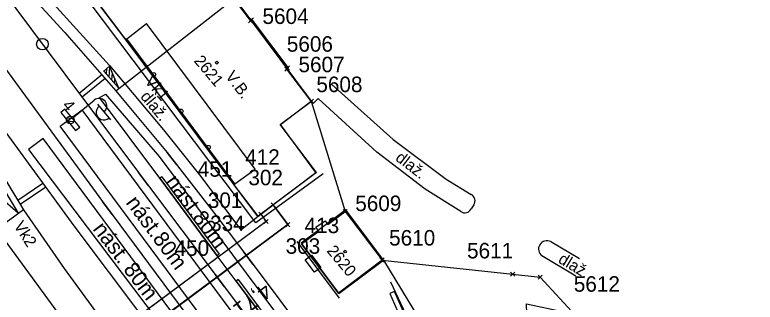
# Model space of a CAD drawing. Extents: x -804166 to -803706, y -1151030 to -1150147.
# Drawn here: x -804085.1 to -803989.6, y -1150250.1 to -1150213 of the extents above; entities that cross this region are included whole.
import ezdxf

# ---------------------------------------------------------------- set-up
doc = ezdxf.new("R2010")
doc.units = 0
for name, color, linetype in [('0381KM032-037P - Vrstva 1', 7, 'Continuous'), ('0381KM032-037P - Vrstva 12', 7, 'Continuous'), ('0381KM032-037P - Vrstva 14', 7, 'Continuous'), ('0381KM032-037P - Vrstva 16', 7, 'Continuous'), ('0381KM032-037P - Vrstva 17', 7, 'Continuous'), ('0381KM032-037P - Vrstva 23', 7, 'Continuous'), ('0381KM032-037P - Vrstva 25', 7, 'Continuous'), ('0381KM032-037P - Vrstva 3', 7, 'Continuous'), ('0381KM032-037P - Vrstva 33', 7, 'Continuous'), ('0381KM032-037P - Vrstva 4', 7, 'Continuous'), ('0381KM032-037P - Vrstva 51', 7, 'Continuous'), ('0381KM032-037P - Vrstva 55', 7, 'Continuous'), ('0381KM032-037P - Vrstva 57', 7, 'Continuous'), ('0381KM032-037P - Vrstva 59', 7, 'Continuous'), ('0381KM032-037P - Vrstva 7', 7, 'Continuous'), ('DZ_CD - CD', 7, 'Continuous'), ('DZ_CD - CD_krizek', 7, 'Continuous'), ('DZ_CD - CD_čísla', 7, 'Continuous'), ('szdc - hran DP', 7, 'Continuous'), ('szdc - szdc_cislo', 7, 'Continuous'), ('szdc - szdc_krizek', 7, 'Continuous'), ('VB - VB', 7, 'Continuous'), ('VB - VB_cislo', 7, 'Continuous'), ('VB - VB_krizek', 7, 'Continuous')]:
    doc.layers.add(name, color=color, linetype=linetype)

msp = doc.modelspace()

# ---------------------------------------------------------------- linework, layer by layer
at = {"layer": '0381KM032-037P - Vrstva 1'}
for points in [[(-804087.926, -1150205.285), (-804078.707, -1150215.283), (-804072.371, -1150222.524), (-804072.077, -1150222.855), (-804071.467, -1150223.584), (-804065.479, -1150230.817), (-804059.467, -1150238.509), (-804055.553, -1150243.678), (-804054.356, -1150245.269), (-804043.889, -1150259.222), (-804035.374, -1150270.613), (-804034.4, -1150271.93), (-804017.97, -1150293.92), (-804002.6, -1150314.46), (-803985.38, -1150337.43), (-803955.87, -1150376.72)], [(-804089.349, -1150206.442), (-804078.67, -1150220.695), (-804069.154, -1150233.375), (-804067.857, -1150235.106), (-804059.282, -1150246.533), (-804058.068, -1150248.156), (-804048.703, -1150260.645), (-804037.85, -1150275.13), (-804021.63, -1150296.76), (-804006.14, -1150317.336), (-803988.978, -1150340.287), (-803981.901, -1150349.725)], [(-804090.387, -1150214.375), (-804086.648, -1150219.546), (-804073.823, -1150237.114), (-804072.555, -1150238.826), (-804064.047, -1150250.31), (-804062.807, -1150251.974), (-804052.288, -1150266.049), (-804042.5, -1150279.11), (-804026.546, -1150300.334), (-804011.272, -1150320.629), (-803993.373, -1150344.487), (-803965.171, -1150382.072), (-803953.841, -1150397.189)], [(-804093.97, -1150217.423), (-804088.165, -1150225.674), (-804077.507, -1150240.279), (-804068.519, -1150252.214), (-804067.312, -1150253.815), (-804055.014, -1150270.122), (-804046.09, -1150281.931), (-804030.046, -1150303.209), (-804014.756, -1150323.518), (-803996.92, -1150347.354), (-803968.884, -1150385.416), (-803942.597, -1150419.033)], [(-804095.554, -1150218.377), (-804090.738, -1150227.081), (-804084.011, -1150238.21), (-804078.761, -1150245.777), (-804072.115, -1150254.848), (-804070.853, -1150256.555), (-804059.975, -1150271.287), (-804049.56, -1150285.37), (-804034.127, -1150306.216), (-804018.794, -1150326.862), (-804001.176, -1150350.631), (-803980.37, -1150378.683), (-803972.82, -1150388.417), (-803965.206, -1150397.597)], [(-804088.45, -1150239.448), (-804070.362, -1150264.071), (-804054.977, -1150285.047), (-804052.95, -1150287.79), (-804037.556, -1150308.636), (-804021.871, -1150329.906), (-804004.483, -1150353.558), (-803990.764, -1150372.094)]]:
    msp.add_lwpolyline(points, dxfattribs=at)
at = {"layer": '0381KM032-037P - Vrstva 12'}
for p, q in [((-804066.16, -1150233.938), (-804066.401, -1150234.117)), ((-804066.16, -1150233.938), (-804058.75, -1150243.944)), ((-804066.401, -1150234.117), (-804058.991, -1150244.123)), ((-804058.75, -1150243.944), (-804058.991, -1150244.123)), ((-804056.315, -1150247.214), (-804056.555, -1150247.394)), ((-804056.315, -1150247.214), (-804040.257, -1150268.603)), ((-804056.555, -1150247.394), (-804040.497, -1150268.783))]:
    msp.add_line(p, q, dxfattribs=at)
at = {"layer": '0381KM032-037P - Vrstva 14'}
for p, q in [((-804074.204, -1150223.733), (-804073.378, -1150223.272)), ((-804079.27, -1150227.397), (-804076.452, -1150225.306)), ((-804028.769, -1150289.524), (-804076.452, -1150225.306)), ((-804031.587, -1150291.616), (-804079.27, -1150227.397)), ((-804081.457, -1150229.022), (-804083.366, -1150230.42)), ((-804033.774, -1150293.241), (-804081.457, -1150229.022)), ((-804083.366, -1150230.42), (-804035.088, -1150294.233))]:
    msp.add_line(p, q, dxfattribs=at)
for points in [[(-804025.083, -1150286.789), (-804066.443, -1150231.313), (-804073.378, -1150223.272)], [(-804026.202, -1150287.61), (-804040.497, -1150268.783), (-804056.555, -1150247.394), (-804058.991, -1150244.123), (-804066.401, -1150234.117), (-804074.204, -1150223.733)]]:
    msp.add_lwpolyline(points, dxfattribs=at)
at = {"layer": '0381KM032-037P - Vrstva 16'}
msp.add_lwpolyline([(-804076.663, -1150208.439), (-804080.541, -1150211.102), (-804072.896, -1150219.59), (-804065.929, -1150227.882), (-804061.293, -1150233.691), (-804055.946, -1150240.785), (-804053.726, -1150239.037)], dxfattribs=at)
at = {"layer": '0381KM032-037P - Vrstva 17'}
msp.add_line((-804033.09, -1150255.012), (-804036.604, -1150247.549), dxfattribs=at)
at = {"layer": '0381KM032-037P - Vrstva 23'}
for p, q in [((-804076.663, -1150208.439), (-804070.854, -1150216.226)), ((-804046.83, -1150224.17), (-804057.749, -1150209.571)), ((-804054.575, -1150213.815), (-804054.464, -1150213.732)), ((-804049.846, -1150219.863), (-804054.464, -1150213.732)), ((-804070.683, -1150216.127), (-804068.144, -1150214.178)), ((-804054.098, -1150232.952), (-804068.144, -1150214.178)), ((-804056.826, -1150234.944), (-804070.739, -1150216.164)), ((-804056.727, -1150234.87), (-804070.683, -1150216.127)), ((-804049.977, -1150219.962), (-804049.846, -1150219.863)), ((-804050.874, -1150227.195), (-804046.83, -1150224.17)), ((-804046.171, -1150233.383), (-804050.874, -1150227.195)), ((-804056.727, -1150234.87), (-804054.098, -1150232.952)), ((-804046.171, -1150233.383), (-804053.726, -1150239.037)), ((-804056.727, -1150234.87), (-804056.827, -1150234.975)), ((-804053.726, -1150239.037), (-804056.827, -1150234.975)), ((-804042.401, -1150238.224), (-804048.187, -1150242.521)), ((-804037.56, -1150244.693), (-804042.401, -1150238.224)), ((-804048.747, -1150242.287), (-804043.271, -1150249.616))]:
    msp.add_line(p, q, dxfattribs=at)
for points in [[(-804045.335, -1150233.577), (-804053.998, -1150239.883), (-804077.772, -1150208.366)], [(-804070.854, -1150216.226), (-804070.854, -1150216.226), (-804070.739, -1150216.164), (-804070.683, -1150216.127)], [(-804048.187, -1150242.521), (-804043.318, -1150249.006), (-804037.56, -1150244.693)]]:
    msp.add_lwpolyline(points, dxfattribs=at)
msp.add_lwpolyline([(-804078.654, -1150225.237), (-804079.177, -1150225.666), (-804077.274, -1150227.98), (-804076.752, -1150227.551)], close=True, dxfattribs=at)
for centre in [(-804067.178, -1150220.749), (-804063.65, -1150225.47), (-804060.146, -1150230.138)]:
    msp.add_circle(centre, 0.25, dxfattribs=at)
at = {"layer": '0381KM032-037P - Vrstva 25'}
for p, q in [((-804077.58, -1150226.29), (-804074.886, -1150224.056)), ((-804074.439, -1150224.595), (-804072.779, -1150226.596)), ((-804078.454, -1150226.704), (-804077.501, -1150226.793)), ((-804078.382, -1150226.334), (-804077.507, -1150226.416))]:
    msp.add_line(p, q, dxfattribs=at)
msp.add_lwpolyline([(-804047.64, -1150244.642), (-804046.836, -1150244.048), (-804045.648, -1150245.658), (-804046.452, -1150246.252), (-804047.64, -1150244.642)], dxfattribs=at)
msp.add_circle((-804077.965, -1150226.609), 0.5, dxfattribs=at)
msp.add_circle((-804077.965, -1150226.609), 0.5, dxfattribs=at)
for centre, start, end in [((-804074.247, -1150224.826), 309.66205, 129.66205), ((-804073.619, -1150225.603), 128.95947, 310.36462)]:
    msp.add_arc(centre, 1, start, end, dxfattribs=at)
at = {"layer": '0381KM032-037P - Vrstva 3'}
for p, q in [((-804072.077, -1150222.855), (-804041.236, -1150198.773)), ((-804073.637, -1150220.313), (-804073.63, -1150220.295)), ((-804073.297, -1150220.702), (-804073.235, -1150219.95)), ((-804072.951, -1150221.097), (-804072.856, -1150219.757)), ((-804072.606, -1150221.492), (-804072.534, -1150220.523)), ((-804072.26, -1150221.887), (-804072.219, -1150221.27)), ((-804071.914, -1150222.282), (-804071.904, -1150222.04)), ((-804084.011, -1150238.21), (-804117.811, -1150262.634)), ((-804084.87, -1150238.335), (-804085.103, -1150238.277))]:
    msp.add_line(p, q, dxfattribs=at)
for points in [[(-804071.701, -1150222.526), (-804072.898, -1150219.655), (-804073.643, -1150220.306), (-804071.701, -1150222.526)], [(-804084.696, -1150238.624), (-804087.103, -1150236.574), (-804086.248, -1150236.056), (-804084.696, -1150238.624)]]:
    msp.add_lwpolyline(points, dxfattribs=at)
at = {"layer": '0381KM032-037P - Vrstva 33'}
msp.add_lwpolyline([(-804035.533, -1150251.745), (-804034.915, -1150251.471), (-804036.128, -1150248.732), (-804036.747, -1150249.006)], close=True, dxfattribs=at)
at = {"layer": '0381KM032-037P - Vrstva 4'}
for p, q in [((-804064.227, -1150232.381), (-804065.479, -1150230.817)), ((-804067.857, -1150235.106), (-804069.154, -1150233.375)), ((-804072.555, -1150238.826), (-804073.823, -1150237.114)), ((-804054.356, -1150245.269), (-804055.553, -1150243.678)), ((-804058.068, -1150248.156), (-804059.282, -1150246.533))]:
    msp.add_line(p, q, dxfattribs=at)
at = {"layer": '0381KM032-037P - Vrstva 51'}
for p, q in [((-804025.879, -1150237.562), (-804026.25, -1150238.06)), ((-804015.963, -1150242.307), (-804012.257, -1150244.47)), ((-804012.731, -1150246.76), (-804017.091, -1150244.14))]:
    msp.add_line(p, q, dxfattribs=at)
for points in [[(-804044.218, -1150222.028), (-804036.309, -1150229.151), (-804029.455, -1150234.23), (-804026.229, -1150236.214)], [(-804027.568, -1150238.429), (-804032.179, -1150235.551), (-804038.398, -1150230.77), (-804045.964, -1150223.831), (-804046.633, -1150224.499), (-804046.894, -1150224.198)], [(-804037.56, -1150244.693), (-804031.308, -1150254.993), (-804027.096, -1150261.05), (-804017.619, -1150257.212), (-804018.951, -1150253.972), (-804019.077, -1150250.328), (-804014.248, -1150251.346)]]:
    msp.add_lwpolyline(points, dxfattribs=at)
for centre, major_axis, ratio, start_param, end_param in [((-804026.692, -1150237.054), (0.085, 0.955), 0.999815, 4.242277, 5.86844), ((-804027.056, -1150237.721), (-0.618, -0.618), 0.999716, 0.15876, 1.957098), ((-804016.456, -1150243.267), (-0.422, -0.994), 0.999309, 3.06867, 6.055029)]:
    msp.add_ellipse(centre, major_axis=major_axis, ratio=ratio, start_param=start_param, end_param=end_param, dxfattribs=at)
at = {"layer": '0381KM032-037P - Vrstva 55'}
for points in [[(-804076.76, -1150208.41), (-804070.92, -1150216.16), (-804056.87, -1150234.96), (-804053.79, -1150239.08), (-804046.26, -1150233.41), (-804050.84, -1150227.18), (-804046.86, -1150224.2), (-804050.01, -1150220.06), (-804049.93, -1150219.91), (-804054.58, -1150213.71), (-804054.7, -1150213.8), (-804057.84, -1150209.6), (-804058.02, -1150209.36), (-804065.16, -1150199.8), (-804065.96, -1150198.88), (-804068.34, -1150200.69), (-804067.42, -1150201.47), (-804069.26, -1150202.82)], [(-804048.13, -1150242.59), (-804045.9, -1150240.94), (-804046.26, -1150240.46), (-804045.09, -1150239.61), (-804044.74, -1150240.08), (-804042.5, -1150238.42), (-804037.73, -1150244.68), (-804043.35, -1150248.97)]]:
    msp.add_lwpolyline(points, close=True, dxfattribs=at)
at = {"layer": '0381KM032-037P - Vrstva 59'}
for centre in [(-804059.051, -1150219.223), (-804042.509, -1150243.599)]:
    msp.add_circle(centre, 0.175, dxfattribs=at)
at = {"layer": '0381KM032-037P - Vrstva 7'}
for p, q in [((-804073.874, -1150220.806), (-804076.804, -1150223.182)), ((-804073.479, -1150221.258), (-804076.443, -1150223.662)), ((-804081.495, -1150234.815), (-804084.753, -1150236.983)), ((-804081.14, -1150235.3), (-804084.442, -1150237.497))]:
    msp.add_line(p, q, dxfattribs=at)
msp.add_circle((-804081.56, -1150216.838), 0.75, dxfattribs=at)
at = {"layer": 'DZ_CD - CD'}
for p, q in [((-804053.386, -1150238.776), (-804051.788, -1150237.573)), ((-804051.788, -1150237.573), (-804053.386, -1150238.776)), ((-804051.788, -1150237.573), (-804049.901, -1150240.116)), ((-804049.901, -1150240.116), (-804051.788, -1150237.573)), ((-804053.386, -1150238.776), (-804052.699, -1150239.702)), ((-804052.699, -1150239.702), (-804078.871, -1150259.126)), ((-804049.901, -1150240.116), (-804076.079, -1150259.544)), ((-804076.079, -1150259.544), (-804049.901, -1150240.116))]:
    msp.add_line(p, q, dxfattribs=at)
at = {"layer": 'DZ_CD - CD_krizek'}
for p, q in [((-804051.523, -1150237.838), (-804052.054, -1150237.308)), ((-804052.054, -1150237.838), (-804051.523, -1150237.308)), ((-804052.434, -1150239.967), (-804052.965, -1150239.437)), ((-804052.965, -1150239.967), (-804052.434, -1150239.437)), ((-804049.636, -1150240.381), (-804050.167, -1150239.851)), ((-804050.167, -1150240.381), (-804049.636, -1150239.851))]:
    msp.add_line(p, q, dxfattribs=at)
at = {"layer": 'szdc - hran DP'}
for p, q in [((-804058.84, -1150208.26), (-804054.7, -1150213.8)), ((-804054.7, -1150213.8), (-804054.58, -1150213.71)), ((-804054.58, -1150213.71), (-804049.93, -1150219.91)), ((-804049.93, -1150219.91), (-804050.01, -1150220.06)), ((-804050.01, -1150220.06), (-804046.86, -1150224.2)), ((-804046.86, -1150224.2), (-804042.5, -1150238.42)), ((-804042.5, -1150238.42), (-804037.73, -1150244.68)), ((-804037.73, -1150244.68), (-804020.87, -1150246.51)), ((-804020.87, -1150246.51), (-804017.32, -1150246.9)), ((-804017.32, -1150246.9), (-804009.55, -1150255.32))]:
    msp.add_line(p, q, dxfattribs=at)
at = {"layer": 'szdc - szdc_krizek'}
for p, q in [((-804054.435, -1150214.065), (-804054.966, -1150213.535)), ((-804054.966, -1150214.065), (-804054.435, -1150213.535)), ((-804054.315, -1150213.975), (-804054.846, -1150213.445)), ((-804054.846, -1150213.975), (-804054.315, -1150213.445)), ((-804049.745, -1150220.325), (-804050.276, -1150219.795)), ((-804050.276, -1150220.325), (-804049.745, -1150219.795)), ((-804049.665, -1150220.175), (-804050.196, -1150219.645)), ((-804050.196, -1150220.175), (-804049.665, -1150219.645)), ((-804046.595, -1150224.465), (-804047.126, -1150223.935)), ((-804047.126, -1150224.465), (-804046.595, -1150223.935)), ((-804042.235, -1150238.685), (-804042.766, -1150238.155)), ((-804042.766, -1150238.685), (-804042.235, -1150238.155)), ((-804037.465, -1150244.945), (-804037.996, -1150244.415)), ((-804037.996, -1150244.945), (-804037.465, -1150244.415)), ((-804020.605, -1150246.775), (-804021.136, -1150246.245)), ((-804021.136, -1150246.775), (-804020.605, -1150246.245)), ((-804017.055, -1150247.165), (-804017.586, -1150246.635)), ((-804017.586, -1150247.165), (-804017.055, -1150246.635))]:
    msp.add_line(p, q, dxfattribs=at)
at = {"layer": 'VB - VB'}
for points in [[(-804051.788, -1150237.573), (-804053.386, -1150238.776), (-804052.699, -1150239.702), (-804078.871, -1150259.126)], [(-804051.788, -1150237.573), (-804049.901, -1150240.116), (-804076.079, -1150259.544)]]:
    msp.add_lwpolyline(points, dxfattribs=at)
at = {"layer": 'VB - VB_krizek'}
for p, q in [((-804051.523, -1150237.838), (-804052.054, -1150237.308)), ((-804052.054, -1150237.838), (-804051.523, -1150237.308)), ((-804053.121, -1150239.041), (-804053.652, -1150238.511)), ((-804053.652, -1150239.041), (-804053.121, -1150238.511)), ((-804052.434, -1150239.967), (-804052.965, -1150239.437)), ((-804052.965, -1150239.967), (-804052.434, -1150239.437)), ((-804049.636, -1150240.381), (-804050.167, -1150239.851)), ((-804050.167, -1150240.381), (-804049.636, -1150239.851))]:
    msp.add_line(p, q, dxfattribs=at)

# ---------------------------------------------------------------- texts
at = {"layer": '0381KM032-037P - Vrstva 1'}
msp.add_text('4,71', height=2, rotation=216.86476, dxfattribs=at).set_placement((-804052.935, -1150247.536))
at = {"layer": '0381KM032-037P - Vrstva 14'}
for s, rotation, p in [('nást.80m', 306.52201, (-804065.751, -1150234.579)), ('nást.80m', 306.59411, (-804070.875, -1150237.299)), ('nást. 80m', 307.10948, (-804075.144, -1150240.704))]:
    msp.add_text(s, height=2, rotation=rotation, dxfattribs=at).set_placement(p)
at = {"layer": '0381KM032-037P - Vrstva 16'}
msp.add_text('dlaž.', height=1.5, rotation=310.03723, dxfattribs=at).set_placement((-804068.998, -1150223.652))
at = {"layer": '0381KM032-037P - Vrstva 23'}
msp.add_text('V.B.', height=1.5, rotation=307.11177, dxfattribs=at).set_placement((-804058.03, -1150220.996))
at = {"layer": '0381KM032-037P - Vrstva 25'}
msp.add_text('4', height=1.5, rotation=309.66205, dxfattribs=at).set_placement((-804079.088, -1150224.783))
at = {"layer": '0381KM032-037P - Vrstva 3'}
for s, rotation, p in [('Vk1', 311.18649, (-804068.455, -1150221.679)), ('Vk2', 302.56097, (-804085.318, -1150240.252))]:
    msp.add_text(s, height=1.5, rotation=rotation, dxfattribs=at).set_placement(p)
at = {"layer": '0381KM032-037P - Vrstva 51'}
for rotation, p in [(322.44789, (-804036.122, -1150231.735)), (328.99761, (-804015.112, -1150244.941))]:
    msp.add_text('dlaž.', height=1.5, rotation=rotation, dxfattribs=at).set_placement(p)
at = {"layer": '0381KM032-037P - Vrstva 57'}
for s, rotation, p in [('2621', 310.03683, (-804062.082, -1150219.027)), ('2620', 309.96136, (-804044.952, -1150243.53))]:
    msp.add_text(s, height=1.5, rotation=rotation, dxfattribs=at).set_placement(p)
at = {"layer": 'DZ_CD - CD_čísla'}
for s, p in [('302', (-804054.981, -1150235.038)), ('301', (-804060.214, -1150237.96)), ('334', (-804059.921, -1150240.938)), ('303', (-804050.174, -1150243.877))]:
    msp.add_text(s, height=2, dxfattribs=at).set_placement(p)
at = {"layer": 'szdc - szdc_cislo'}
for s, p in [('5604', (-804053.161, -1150214.231)), ('5606', (-804050.019, -1150217.807)), ('5607', (-804048.513, -1150220.458)), ('5608', (-804046.207, -1150223.022)), ('5609', (-804041.19, -1150238.366)), ('5610', (-804036.818, -1150242.814)), ('5611', (-804026.761, -1150244.47)), ('5612', (-804012.984, -1150248.771))]:
    msp.add_text(s, height=2, dxfattribs=at).set_placement(p)
at = {"layer": 'VB - VB_cislo'}
for s, p in [('412', (-804055.392, -1150232.399)), ('451', (-804061.513, -1150233.934)), ('413', (-804047.729, -1150241.216)), ('450', (-804064.504, -1150244.141))]:
    msp.add_text(s, height=2, dxfattribs=at).set_placement(p)

doc.saveas('drawing.dxf')
